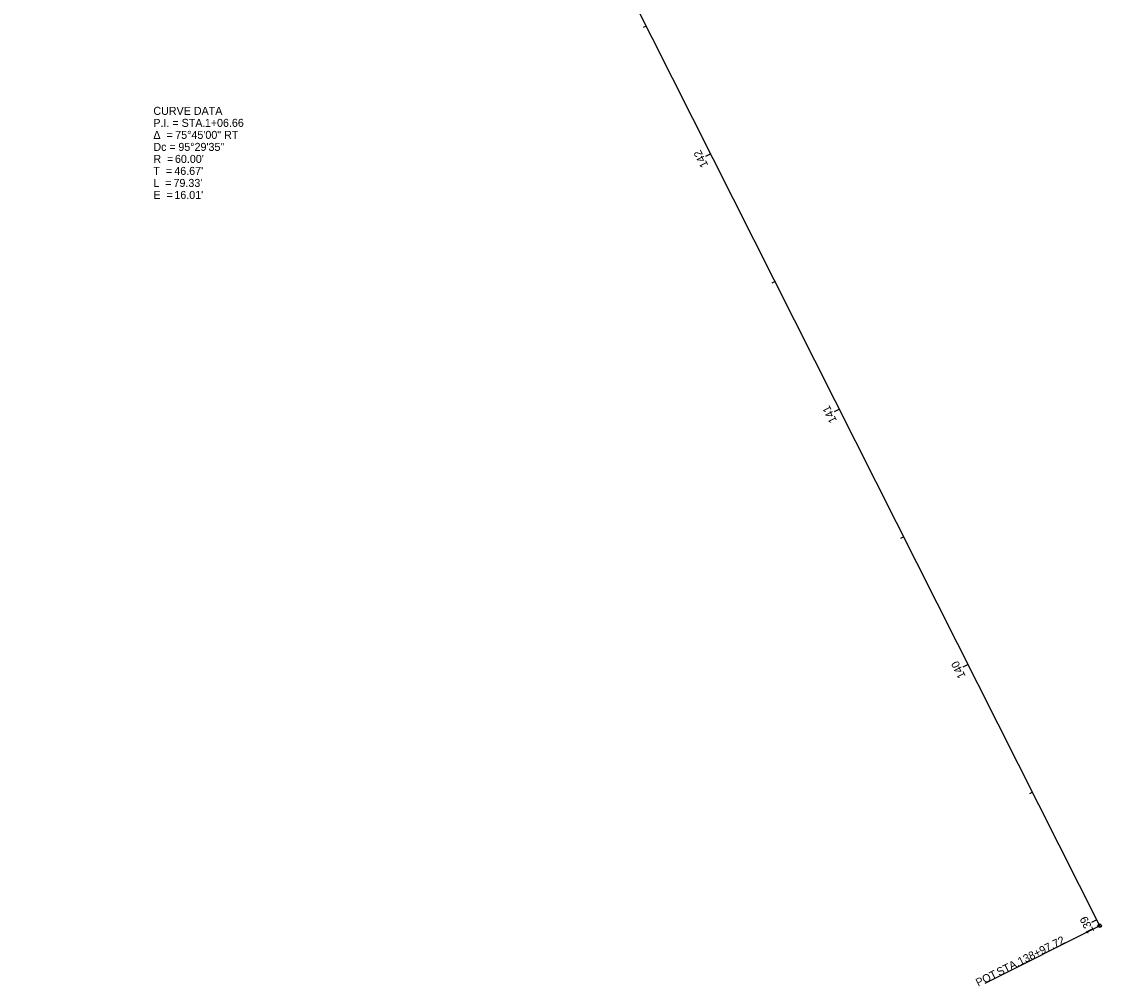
# Model space of a CAD drawing. Extents: x 1359387 to 1360093, y 668188 to 669559.
# Drawn here: x 1359715.5 to 1360093.1, y 668188 to 668525.3 of the extents above; entities that cross this region are included whole.
import ezdxf

# ---------------------------------------------------------------- set-up
doc = ezdxf.new("R2010")
doc.units = 0
for name, color, linetype in [('Default', 7, 'Continuous'), ('SH_Data', 7, 'Continuous'), ('SH_Major_Grid_Line', 7, 'Continuous'), ('SH_Named_Boundary', 7, 'Continuous'), ('SH_Text', 7, 'Continuous')]:
    doc.layers.add(name, color=color, linetype=linetype)

msp = doc.modelspace()

# ---------------------------------------------------------------- linework, layer by layer
at = {"layer": 'Default'}
msp.add_line((1360092.49, 668209.18), (1359715.49, 668957.31), dxfattribs=at)
at = {"layer": 'SH_Data'}
msp.add_line((1360092.49, 668209.18), (1360052.3, 668188.93), dxfattribs=at)
msp.add_circle((1360092.49, 668209.18), 0.6, dxfattribs=at)
at = {"layer": 'SH_Named_Boundary'}
msp.add_line((1360092.49, 668209.18), (1359715.49, 668957.31), dxfattribs=at)
at = {"layer": 'SH_Text'}
for p, q in [((1359933.96, 668523.78), (1359932.89, 668523.24)), ((1359956.46, 668479.12), (1359954.67, 668478.22)), ((1359978.96, 668434.47), (1359977.89, 668433.93)), ((1360001.46, 668389.82), (1359999.67, 668388.92)), ((1360023.96, 668345.17), (1360022.89, 668344.63)), ((1360046.46, 668300.52), (1360044.68, 668299.62)), ((1360068.96, 668255.87), (1360067.89, 668255.33)), ((1360091.46, 668211.22), (1360089.68, 668210.32))]:
    msp.add_line(p, q, dxfattribs=at)

# ---------------------------------------------------------------- texts
at = {"layer": 'SH_Data'}
for s, p in [('138+97.72', (1360064.71, 668195.22)), (' STA. ', (1360056.38, 668191.03)), ('POT', (1360050.01, 668187.82))]:
    msp.add_text(s, height=2.8, rotation=26.7446, dxfattribs=at).set_placement(p)
at = {"layer": 'SH_Major_Grid_Line'}
for s, p in [('CURVE DATA', (1359761.57, 668492.73)), ('P.I. = STA. ', (1359761.57, 668488.53)), ('1+06.66', (1359779.56, 668488.53)), ('Δ  = ', (1359761.57, 668484.33)), ('75°45\'00" RT', (1359769.22, 668484.33)), ('Dc = ', (1359761.57, 668480.13)), ('95°29\'35"', (1359770.31, 668480.13)), ('R  = ', (1359761.57, 668475.93)), ("60.00'", (1359769.11, 668475.93)), ('T  = ', (1359761.57, 668471.73)), ("46.67'", (1359768.89, 668471.73)), ('L  = ', (1359761.57, 668467.53)), ("79.33'", (1359768.61, 668467.53)), ('E  = ', (1359761.57, 668463.33)), ("16.01'", (1359768.91, 668463.33))]:
    msp.add_text(s, height=2.8, rotation=360, dxfattribs=at).set_placement(p)
at = {"layer": 'SH_Text'}
for s, p in [('142', (1359955.67, 668475.13)), ('141', (1360000.68, 668385.82)), ('140', (1360045.7, 668296.48)), ('139', (1360090.68, 668207.21))]:
    msp.add_text(s, height=2.8, rotation=116.7446, dxfattribs=at).set_placement(p)

doc.saveas('drawing.dxf')
